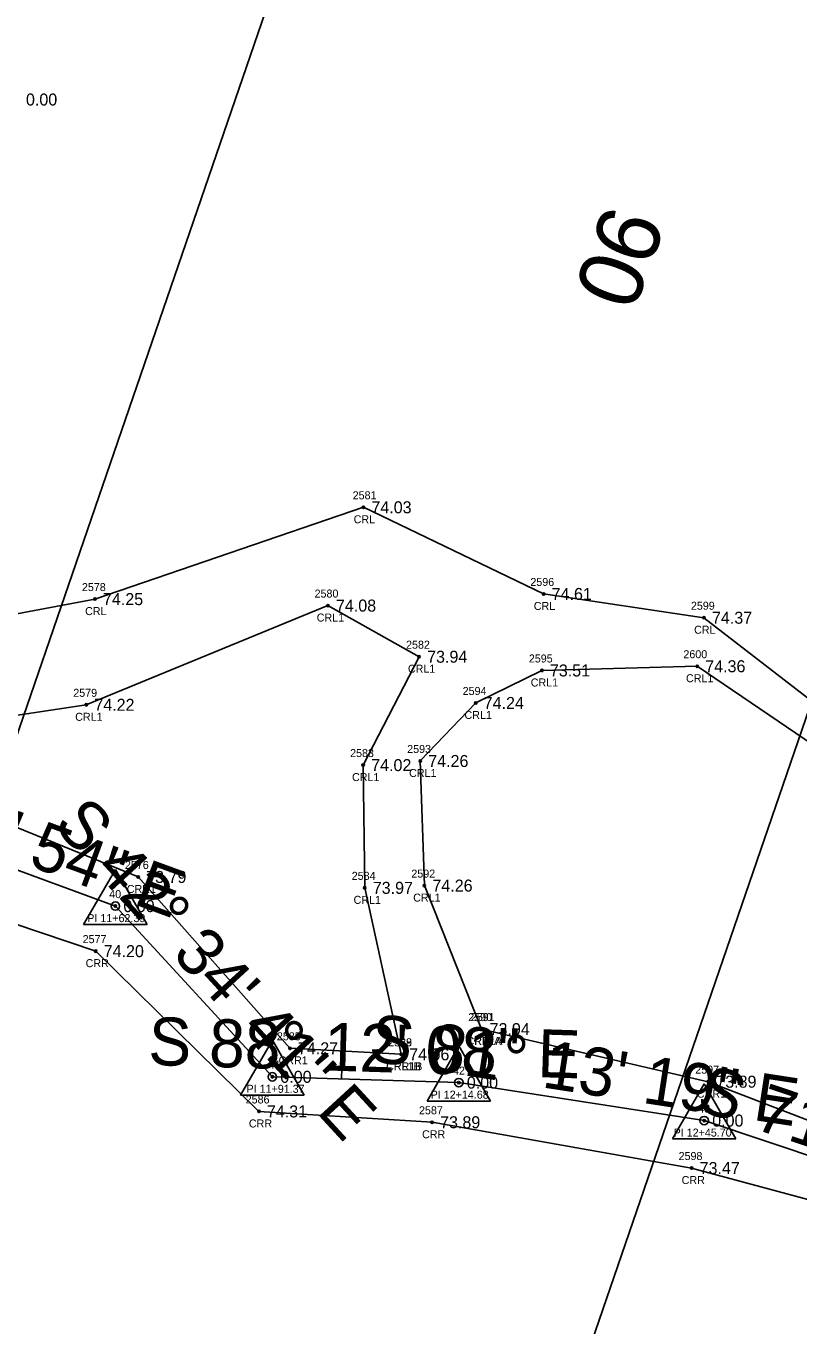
# Model space of a CAD drawing. Extents: x 2139392 to 2143384, y 505395 to 510520.
# Drawn here: x 2141025.8 to 2141122.3, y 508983.1 to 509145.6 of the extents above; entities that cross this region are included whole.
import ezdxf

# ---------------------------------------------------------------- set-up
doc = ezdxf.new("R2010")
doc.units = 0
for name, color, linetype in [('RD_EV_EX_Wetlands', 7, 'Continuous'), ('RD_EX_H2O', 7, 'Continuous'), ('RD_EX_H2O_txCode', 7, 'Continuous'), ('RD_EX_TX_DV_Prop_ELEV', 7, 'Continuous'), ('RD_EX_TX_H2O_ELEV', 7, 'Continuous'), ('RD_EX_VEG', 7, 'Continuous'), ('RD_HC_Cl', 7, 'Continuous'), ('RD_HC_Data', 7, 'Continuous'), ('RD_HC_Data_Tic', 7, 'Continuous'), ('RD_HC_Survey_ELEV', 7, 'Continuous'), ('RD_HC_TX_Sta50', 7, 'Continuous'), ('RD_HC_txCode', 7, 'Continuous'), ('RD_SMD_Locator', 7, 'Continuous')]:
    doc.layers.add(name, color=color, linetype=linetype)

msp = doc.modelspace()

# ---------------------------------------------------------------- linework, layer by layer
at = {"layer": 'RD_EV_EX_Wetlands'}
msp.add_lwpolyline([(2141075.3, 509306.14), (2141106.63, 509288.93), (2141187.92, 509247.51), (2140965, 508598.64), (2140811.93, 508219.91), (2140776.47, 508059.54), (2140705.92, 508079.01), (2140681.94, 508086.65), (2140661.45, 508087.99), (2140646.39, 508098.18), (2140717.89, 508303.96)], dxfattribs=at)
at = {"layer": 'RD_EX_H2O'}
for points in [[(2140988.5, 509071.15), (2140995.33, 509067.35), (2140996.76, 509067.73), (2140999.1, 509067.34), (2141034.38, 509073.97), (2141067.92, 509085.44), (2141090.44, 509074.61), (2141110.47, 509071.64), (2141125.77, 509059.81), (2141130.36, 509054.36)], [(2141002.62, 509056.13), (2141033.3, 509060.76), (2141063.49, 509073.16), (2141074.88, 509066.77), (2141067.89, 509053.23), (2141068.09, 509037.89), (2141072.64, 509017.09)], [(2141082.69, 509020.24), (2141075.54, 509038.17), (2141075.02, 509053.74), (2141081.95, 509060.99), (2141090.22, 509065.05), (2141109.63, 509065.58), (2141124.15, 509055.72), (2141130.36, 509054.36)], [(2141002.62, 509056.13), (2141002.29, 509054.53), (2141039.78, 509039.25), (2141058.74, 509017.84), (2141072.64, 509017.09)], [(2140979.84, 509045.53), (2140988.49, 509044.65), (2140996.91, 509042.64), (2141034.47, 509029.98), (2141054.86, 509009.95), (2141076.5, 509008.6), (2141108.93, 509002.88), (2141157.17, 508989.85), (2141167.48, 508991.01), (2141188.81, 509012.46), (2141188.28, 509016.58)], [(2141082.69, 509020.24), (2141111.01, 509013.67), (2141158.94, 508995.2), (2141180.37, 509014.56), (2141188.28, 509016.58)]]:
    msp.add_lwpolyline(points, dxfattribs=at)
at = {"layer": 'RD_EX_VEG'}
msp.add_lwpolyline([(2141197.74, 509262.45), (2141108.66, 509301.7), (2140947.3, 508831.92), (2140798.26, 508440.01), (2140718.9, 508193.9), (2140671.92, 508048.02), (2140772.34, 507989.74)], dxfattribs=at)
at = {"layer": 'RD_HC_Cl'}
for p, q in [((2141000.3, 509049.02), (2141036.93, 509035.61)), ((2141036.93, 509035.61), (2141056.54, 509014.28)), ((2141056.54, 509014.28), (2141079.84, 509013.55)), ((2141079.84, 509013.55), (2141110.5, 509008.81)), ((2141110.5, 509008.81), (2141159.16, 508992.54))]:
    msp.add_line(p, q, dxfattribs=at)
at = {"layer": 'RD_HC_Data'}
for p, q in [((2141032.96, 509033.32), (2141036.94, 509040.2)), ((2141036.94, 509040.2), (2141040.9, 509033.32)), ((2141032.96, 509033.32), (2141040.9, 509033.32)), ((2141052.57, 509011.99), (2141056.54, 509018.87)), ((2141056.54, 509018.87), (2141060.51, 509011.99)), ((2141075.87, 509011.25), (2141079.84, 509018.13)), ((2141079.84, 509018.13), (2141083.81, 509011.25)), ((2141106.53, 509006.52), (2141110.5, 509013.4)), ((2141110.5, 509013.4), (2141114.47, 509006.52)), ((2141052.57, 509011.99), (2141060.51, 509011.99)), ((2141075.87, 509011.25), (2141083.81, 509011.25)), ((2141106.53, 509006.52), (2141114.47, 509006.52))]:
    msp.add_line(p, q, dxfattribs=at)
for centre in [(2141036.93, 509035.61), (2141056.54, 509014.28), (2141079.84, 509013.55), (2141110.5, 509008.81)]:
    msp.add_circle(centre, 0.529, dxfattribs=at)
at = {"layer": 'RD_HC_Data_Tic'}
msp.add_line((2141065.17, 509014.01), (2141065.29, 509018.01), dxfattribs=at)
at = {"layer": 'RD_SMD_Locator'}
for centre in [(2141067.92, 509085.44), (2141034.38, 509073.97), (2141090.44, 509074.61), (2141063.49, 509073.16), (2141110.47, 509071.64), (2141074.88, 509066.77), (2141090.22, 509065.05), (2141109.63, 509065.58), (2141081.95, 509060.99), (2141033.3, 509060.76), (2141067.89, 509053.23), (2141075.02, 509053.74), (2141039.78, 509039.25), (2141075.54, 509038.17), (2141068.09, 509037.89), (2141036.93, 509035.61), (2141034.47, 509029.98), (2141082.69, 509020.24), (2141082.69, 509020.24), (2141058.74, 509017.84), (2141072.64, 509017.09), (2141072.64, 509017.09), (2141056.54, 509014.28), (2141079.84, 509013.55), (2141111.01, 509013.67), (2141054.86, 509009.95), (2141110.5, 509008.81), (2141076.5, 509008.6), (2141108.93, 509002.88)]:
    msp.add_circle(centre, 0.15, dxfattribs=at)

# ---------------------------------------------------------------- texts
at = {"layer": 'RD_EX_H2O_txCode'}
for s, p in [('2581', (2141066.58, 509086.44)), ('CRL', (2141066.7, 509083.44)), ('2578', (2141032.75, 509074.97)), ('2596', (2141088.78, 509075.61)), ('2580', (2141061.82, 509074.16)), ('CRL', (2141033.15, 509071.97)), ('CRL', (2141089.21, 509072.61)), ('2599', (2141108.84, 509072.64)), ('CRL1', (2141062.09, 509071.16)), ('CRL', (2141109.24, 509069.64)), ('2582', (2141073.25, 509067.77)), ('2600', (2141107.9, 509066.58)), ('2595', (2141088.59, 509066.05)), ('CRL1', (2141073.48, 509064.77)), ('CRL1', (2141108.23, 509063.58)), ('2579', (2141031.67, 509061.76)), ('2594', (2141080.32, 509061.99)), ('CRL1', (2141088.83, 509063.05)), ('CRL1', (2141031.91, 509058.76)), ('CRL1', (2141080.55, 509058.99)), ('2583', (2141066.26, 509054.23)), ('2593', (2141073.39, 509054.74)), ('CRL1', (2141066.5, 509051.23)), ('CRL1', (2141073.63, 509051.74)), ('2576', (2141038.12, 509040.25)), ('2584', (2141066.46, 509038.89)), ('2592', (2141073.91, 509039.17)), ('CRR1', (2141038.36, 509037.25)), ('CRL1', (2141066.69, 509035.89)), ('CRL1', (2141074.14, 509036.17)), ('2577', (2141032.84, 509030.98)), ('CRR', (2141033.21, 509027.98)), ('2590', (2141081.02, 509021.24)), ('2591', (2141081.34, 509021.24)), ('2585', (2141057.11, 509018.84)), ('2588', (2141071.01, 509018.09)), ('2589', (2141071.01, 509018.09)), ('CRR1A', (2141080.78, 509018.24)), ('CRL1A', (2141080.81, 509018.24)), ('CRR1', (2141057.32, 509015.84)), ('CRR1B', (2141070.75, 509015.09)), ('CRL1B', (2141070.77, 509015.09)), ('2597', (2141109.38, 509014.67)), ('CRR1', (2141109.59, 509011.67)), ('2586', (2141053.21, 509010.95)), ('2587', (2141074.87, 509009.6)), ('CRR', (2141053.61, 509007.95)), ('CRR', (2141075.25, 509006.6)), ('2598', (2141107.3, 509003.88)), ('CRR', (2141107.68, 509000.88))]:
    msp.add_text(s, height=1, dxfattribs=at).set_placement(p)
at = {"layer": 'RD_EX_TX_DV_Prop_ELEV'}
msp.add_text('0.00', height=1.5, dxfattribs=at).set_placement((2141025.76, 509135.64))
at = {"layer": 'RD_EX_TX_H2O_ELEV'}
for s, p in [('74.03', (2141068.92, 509084.69)), ('74.25', (2141035.38, 509073.22)), ('74.08', (2141064.49, 509072.41)), ('74.61', (2141091.44, 509073.86)), ('74.37', (2141111.47, 509070.89)), ('73.94', (2141075.88, 509066.02)), ('73.51', (2141091.22, 509064.3)), ('74.36', (2141110.63, 509064.83)), ('74.22', (2141034.3, 509060.01)), ('74.24', (2141082.95, 509060.24)), ('74.26', (2141076.02, 509052.99)), ('74.02', (2141068.89, 509052.48)), ('73.79', (2141040.78, 509038.5)), ('73.97', (2141069.09, 509037.14)), ('74.26', (2141076.54, 509037.42)), ('74.20', (2141035.47, 509029.23)), ('73.94', (2141083.69, 509019.49)), ('73.94', (2141083.69, 509019.49)), ('74.27', (2141059.74, 509017.09)), ('74.06', (2141073.64, 509016.34)), ('74.06', (2141073.64, 509016.34)), ('73.89', (2141112.01, 509012.92)), ('74.31', (2141055.86, 509009.2)), ('73.89', (2141077.5, 509007.85)), ('73.47', (2141109.93, 509002.13))]:
    msp.add_text(s, height=1.5, dxfattribs=at).set_placement(p)
at = {"layer": 'RD_HC_Data'}
for s, rotation, p in [('S 69%%d 53\' 54" E', 339.8984, (2140993.38, 509052.62)), ('S 42%%d 34\' 41" E', 312.5779, (2141029.04, 509045.68)), ('S 81%%d 13\' 19" E', 351.2221, (2141068.4, 509016.33)), ('S 88%%d 12\' 08" E', 358.2021, (2141040.99, 509015.77)), ('S 71%%d 30\' 31" E', 341.5085, (2141109.31, 509010.26))]:
    msp.add_text(s, height=6, rotation=rotation, dxfattribs=at).set_placement(p)
at = {"layer": 'RD_HC_Survey_ELEV'}
for p in [(2141037.93, 509034.86), (2141057.54, 509013.53), (2141080.84, 509012.8), (2141111.5, 509008.06)]:
    msp.add_text('0.00', height=1.5, dxfattribs=at).set_placement(p)
at = {"layer": 'RD_HC_TX_Sta50'}
msp.add_text('90', height=8, rotation=249.9158, dxfattribs=at).set_placement((2141098.22, 509123.62))
at = {"layer": 'RD_HC_txCode'}
for s, p in [('40', (2141036.16, 509036.61)), ('PI 11+62.39', (2141033.42, 509033.61)), ('41', (2141056.09, 509015.28)), ('42', (2141079.11, 509014.55)), ('PI 11+91.37', (2141053.32, 509012.28)), ('PI 12+14.68', (2141076.32, 509011.55)), ('43', (2141109.76, 509009.81)), ('PI 12+45.70', (2141106.68, 509006.81))]:
    msp.add_text(s, height=1, dxfattribs=at).set_placement(p)

doc.saveas('drawing.dxf')
